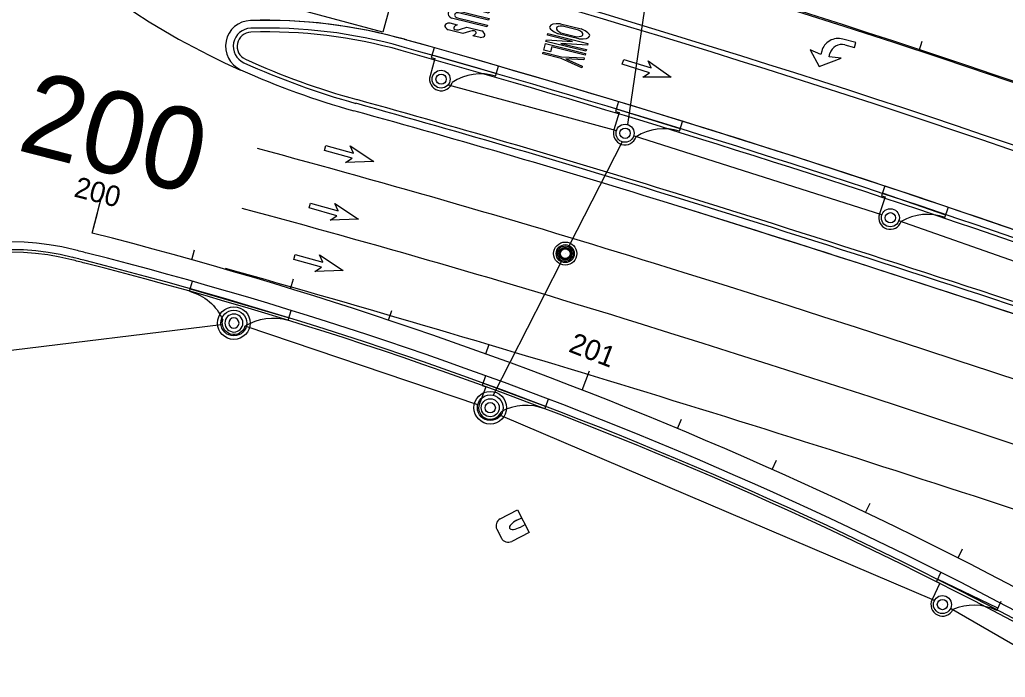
# Model space of a CAD drawing. Extents: x 468143 to 491361, y 1438528 to 1468730.
# Drawn here: x 487025 to 487216.5, y 1467246.7 to 1467374.4 of the extents above; entities that cross this region are included whole.
import ezdxf

# ---------------------------------------------------------------- set-up
doc = ezdxf.new("R2010")
doc.units = 0
doc.layers.add('Default', color=7, linetype='Continuous')
doc.layers.add('Xreference_dp', color=7, linetype='Continuous')

# ---------------------------------------------------------------- blocks, each defined once
blk = doc.blocks.new('POINT_DISPLAY')
at = {"layer": 'Default'}
blk.add_line((0, 0), (0, 0), dxfattribs=at)
blk = doc.blocks.new('InltCurb1_35')
at = {"layer": 'Default'}
for p, q in [((2.25, 2), (2.25, 5.5)), ((-10, 2), (-10, 0)), ((3, 2), (2.25, 2)), ((3, 0), (3, 2)), ((-10, 1.5), (3, 1.5))]:
    blk.add_line(p, q, dxfattribs=at)
for radius in [1.75, 1]:
    blk.add_circle((0, 5.5), radius, dxfattribs=at)
for centre, radius, start, end in [((0, 5.5), 2.25, 0, 180), ((-9.85, 12), 10, 269.1432, 319.4677)]:
    blk.add_arc(centre, radius, start, end, dxfattribs=at)
for p in [(0, 7.75), (-1.6, 6.2), (-1.22, 6.76), (-0.66, 7.12), (0, 7.25), (0, 7.25), (0.7, 7.1), (1.26, 6.72), (1.62, 6.16), (-1.75, 5.5), (-1.75, 5.5), (-1.62, 4.84), (-1.26, 4.28), (-0.7, 3.9), (0, 5.5), (0, 5.5), (0.66, 3.88), (1.22, 4.24), (1.6, 4.8), (1.75, 5.5), (1.75, 5.5), (0, 3.75), (0, 3.75), (0, 0), (0, 0)]:
    blk.add_blockref('POINT_DISPLAY', p, dxfattribs=at)
blk = doc.blocks.new('InltCurb2_35')
at = {"layer": 'Default'}
for p, q in [((-10, 2), (-10, 0)), ((10, 2), (10, 0)), ((-10, 1.5), (10, 1.5))]:
    blk.add_line(p, q, dxfattribs=at)
for radius in [1.75, 1]:
    blk.add_circle((0, 5.5), radius, dxfattribs=at)
for centre, radius, start, end in [((0, 5.5), 2.25, 0, 180), ((-9.85, 12), 10, 269.1432, 319.4677), ((9.85, 12), 10, 220.5323, 270.8568)]:
    blk.add_arc(centre, radius, start, end, dxfattribs=at)
for p in [(0, 7.75), (-1.6, 6.2), (-1.22, 6.76), (-0.66, 7.12), (0, 7.25), (0, 7.25), (0.7, 7.1), (1.26, 6.72), (1.62, 6.16), (-1.75, 5.5), (-1.75, 5.5), (-1.62, 4.84), (-1.26, 4.28), (-0.7, 3.9), (0, 5.5), (0, 5.5), (0.66, 3.88), (1.22, 4.24), (1.6, 4.8), (1.75, 5.5), (1.75, 5.5), (0, 3.75), (0, 3.75), (0, 0), (0, 0)]:
    blk.add_blockref('POINT_DISPLAY', p, dxfattribs=at)
blk = doc.blocks.new('MH2')
at = {"layer": 'Default'}
for p, q in [((-1.25, 0.03), (-1.05, 0.03)), ((-0.9, 0.87), (-0.76, 0.73)), ((-0.87, 0.9), (-0.73, 0.76)), ((-0.03, 1.25), (-0.03, 1.05)), ((0.03, 1.25), (0.03, 1.05)), ((0.87, 0.9), (0.73, 0.76)), ((0.9, 0.87), (0.76, 0.73)), ((1.05, 0.03), (1.25, 0.03)), ((-1.25, -0.03), (-1.05, -0.03)), ((-0.76, -0.73), (-0.9, -0.87)), ((-0.73, -0.76), (-0.87, -0.9)), ((-0.03, -1.05), (-0.03, -1.25)), ((0.03, -1.05), (0.03, -1.25)), ((0.73, -0.76), (0.87, -0.9)), ((0.76, -0.73), (0.9, -0.87)), ((1.05, -0.03), (1.25, -0.03))]:
    blk.add_line(p, q, dxfattribs=at)
for radius in [1.5, 1.25, 1.05, 1, 0.958]:
    blk.add_circle((0, 0), radius, dxfattribs=at)
for p in [(-1, 0), (-0.71, 0.71), (0, 1.5), (0, 1), (0, 0), (0, 0), (0, 0), (0.71, 0.71), (1, 0), (-0.71, -0.71), (0, -1), (0, -1.5), (0.71, -0.71)]:
    blk.add_blockref('POINT_DISPLAY', p, dxfattribs=at)
blk = doc.blocks.new('PBottom35Dia')
at = {"layer": 'Default'}
for radius in [2.25, 1.75, 1.75]:
    blk.add_circle((0, 0), radius, dxfattribs=at)
for p in [(-1.75, 0), (-1.75, 0), (-1.6, 0.7), (-1.22, 1.26), (-0.66, 1.62), (0, 1.75), (0, 1.75), (0, 1.75), (0, 0), (0, 0), (0.7, 1.6), (1.26, 1.22), (1.62, 0.66), (1.75, 0), (1.75, 0), (-1.62, -0.66), (-1.26, -1.22), (-0.7, -1.6), (0, -1.75), (0, -1.75), (0, -1.75), (0.66, -1.62), (1.22, -1.26), (1.6, -0.7)]:
    blk.add_blockref('POINT_DISPLAY', p, dxfattribs=at)
blk = doc.blocks.new('MESS12ECP4S')
at = {"layer": 'Default'}
for p, q in [((0.96, 2.29), (-0.96, 2.29)), ((-2.46, -3.03), (-2.46, 0.79)), ((2.46, 0.79), (2.46, -3.03)), ((2.46, -3.03), (-2.46, -3.03)), ((-0.75, -2), (-0.75, -3.03)), ((0.75, -2), (0.75, -3.03))]:
    blk.add_line(p, q, dxfattribs=at)
for centre, start, end in [((-0.96, 0.79), 90, 180), ((0.96, 0.79), 0, 90)]:
    blk.add_arc(centre, 1.5, start, end, dxfattribs=at)
blk.add_ellipse((0, -2), major_axis=(0, 2), ratio=0.375, start_param=4.712422, end_param=7.853962, dxfattribs=at)
for p in [(0, 2.29), (0, 1.97), (0, 0), (0, 0), (0, -3.03)]:
    blk.add_blockref('POINT_DISPLAY', p, dxfattribs=at)
blk = doc.blocks.new('JBottom50Dia')
at = {"layer": 'Default'}
for radius in [3.17, 2.5, 2.5]:
    blk.add_circle((0, 0), radius, dxfattribs=at)
for p in [(-0.94, 2.32), (0, 2.5), (0, 2.5), (0, 2.5), (1.01, 2.29), (-2.29, 1.01), (-1.74, 1.79), (0, 0), (0, 0), (0, 0), (1.79, 1.74), (2.32, 0.94), (2.5, 0), (2.5, 0), (-2.5, 0), (-2.5, 0), (-2.32, -0.94), (-1.79, -1.74), (1.74, -1.79), (2.29, -1.01), (-1.01, -2.29), (0, -2.5), (0, -2.5), (0, -2.5), (0.94, -2.32)]:
    blk.add_blockref('POINT_DISPLAY', p, dxfattribs=at)
blk = doc.blocks.new('DALeftTurn_1')
at = {"layer": 'Default'}
for points in [[(5.67, 3.17), (2, 0.5), (4.33, 0.83), (4.33, 0.17)], [(6, 0.17), (6, 0.83), (8.25, 0.5), (5.67, 3.17)], [(2, -2.17), (0, -2.17), (0, -3.17), (2.67, -3.17)]]:
    blk.add_lwpolyline(points, dxfattribs=at)
for centre, radius in [((2, 0.17), 2.33), ((2.67, 0.17), 3.33)]:
    blk.add_arc(centre, radius, 270, 0, dxfattribs=at)
blk = doc.blocks.new('DAMerge_2')
at = {"layer": 'Default'}
blk.add_lwpolyline([(0.71, -4.09), (0, -3.39), (3.95, 0.56), (2.42, 0.68), (7.31, 3.21), (4.77, -1.68), (4.66, -0.15), (0.71, -4.09)], dxfattribs=at)
blk = doc.blocks.new('BUS_7')
at = {"layer": 'Default'}
for p, q in [((0, 2.46), (0, 3.17)), ((0, 3.17), (8, 3.17)), ((3.33, 2.83), (1.33, 2.83)), ((1.33, 2.83), (1.33, 2.58)), ((3.33, 2.58), (3.33, 2.83)), ((6.67, 2.83), (4.67, 2.83)), ((4.67, 2.83), (4.67, 2.58)), ((6.67, 2.58), (6.67, 2.83)), ((8, 3.17), (8, 2.46)), ((3.38, 1.83), (0.62, 1.83)), ((0.97, 0.86), (8, 0.86)), ((8, 0.5), (2, 0.5)), ((7.38, 1.83), (4.62, 1.83)), ((8, 0.86), (8, 0.5)), ((0.8, -1.83), (2.26, -1.83)), ((8, -0.83), (0.89, -0.83)), ((2, -0.5), (8, -0.5)), ((3.08, -2.5), (4.23, -1.83)), ((4.23, -1.83), (7.2, -1.83)), ((8, -0.5), (8, -0.83)), ((3.77, -3.17), (0.8, -3.17)), ((4.93, -2.5), (3.77, -3.17)), ((7.2, -3.17), (5.74, -3.17))]:
    blk.add_line(p, q, dxfattribs=at)
for centre, major_axis, ratio, start_param, end_param in [((2, 2.83), (-2.08, 0), 0.64, 0.283794, 0.848062), ((2.33, 2.83), (-1.17, 0), 0.428571, 0.5411, 2.600493), ((2, 2.83), (-2.08, 0), 0.64, 2.293531, 2.857799), ((6, 2.83), (2.08, 0), 0.64, 3.425387, 3.989655), ((5.67, 2.83), (1.17, 0), 0.428571, 3.682692, 5.742086), ((6, 2.83), (2.08, 0), 0.64, 5.435123, 5.999391), ((2, 0), (2, 0), 0.5, 2.110653, 4.126703), ((2, 0), (0.667, 0), 0.75, 1.570796, 4.712389), ((2, -2.5), (-2, 0), 0.416667, 5.35589, 7.210481), ((2.67, -2.17), (-0.877, -0.48), 0.5, 4.914869, 8.056461), ((6, -2.5), (2, 0), 0.416667, 5.35589, 7.210481), ((5.33, -2.83), (-0.869, -0.495), 0.5, 1.760499, 4.902092)]:
    blk.add_ellipse(centre, major_axis=major_axis, ratio=ratio, start_param=start_param, end_param=end_param, dxfattribs=at)
blk = doc.blocks.new('BikeONLY_2')
at = {"layer": 'Default'}
for p, q in [((0.97, 1.833), (3.03, 1.833)), ((2.8, 1.667), (1.2, 1.667)), ((1.2, 1), (2.8, 1)), ((3.03, 0.833), (0.97, 0.833))]:
    blk.add_line(p, q, dxfattribs=at)
for points in [[(0, -0.167), (0, 0), (2.5, 0.458), (0, 0.458), (0, 0.625), (4, 0.625), (4, 0.458), (1.45, 0), (4, 0), (4, -0.167), (0, -0.167)], [(0.667, -1.042), (0, -1.042), (0, -0.375), (4, -0.375), (4, -0.542), (0.667, -0.542), (0.667, -1.042)], [(4, -1.833), (1.833, -1.417), (0, -1.417), (0, -1.25), (1.833, -1.25), (4, -0.833), (4, -1.003), (2.283, -1.333), (4, -1.664), (4, -1.833)]]:
    blk.add_lwpolyline(points, dxfattribs=at)
for major_axis, ratio, start_param, end_param in [((2, 0), 0.291667, 2.111896, 4.171289), ((1.333, 0), 0.3125, 2.214297, 4.068888), ((1.333, 0), 0.3125, 5.35589, 7.210481), ((2, 0), 0.291667, 5.253489, 7.312882)]:
    blk.add_ellipse((2, 1.333), major_axis=major_axis, ratio=ratio, start_param=start_param, end_param=end_param, dxfattribs=at)
blk = doc.blocks.new('DAMerge_6')
at = {"layer": 'Default'}
blk.add_lwpolyline([(0.71, -4.09), (0, -3.39), (3.95, 0.56), (2.42, 0.68), (7.31, 3.21), (4.77, -1.68), (4.66, -0.15), (0.71, -4.09)], dxfattribs=at)
blk = doc.blocks.new('BUS_8')
at = {"layer": 'Default'}
for p, q in [((0, 2.46), (0, 3.17)), ((0, 3.17), (8, 3.17)), ((3.33, 2.83), (1.33, 2.83)), ((1.33, 2.83), (1.33, 2.58)), ((3.33, 2.58), (3.33, 2.83)), ((6.67, 2.83), (4.67, 2.83)), ((4.67, 2.83), (4.67, 2.58)), ((6.67, 2.58), (6.67, 2.83)), ((8, 3.17), (8, 2.46)), ((3.38, 1.83), (0.62, 1.83)), ((0.97, 0.86), (8, 0.86)), ((8, 0.5), (2, 0.5)), ((7.38, 1.83), (4.62, 1.83)), ((8, 0.86), (8, 0.5)), ((0.8, -1.83), (2.26, -1.83)), ((8, -0.83), (0.89, -0.83)), ((2, -0.5), (8, -0.5)), ((3.08, -2.5), (4.23, -1.83)), ((4.23, -1.83), (7.2, -1.83)), ((8, -0.5), (8, -0.83)), ((3.77, -3.17), (0.8, -3.17)), ((4.93, -2.5), (3.77, -3.17)), ((7.2, -3.17), (5.74, -3.17))]:
    blk.add_line(p, q, dxfattribs=at)
for centre, major_axis, ratio, start_param, end_param in [((2, 2.83), (-2.08, 0), 0.64, 0.283794, 0.848062), ((2.33, 2.83), (-1.17, 0), 0.428571, 0.5411, 2.600493), ((2, 2.83), (-2.08, 0), 0.64, 2.293531, 2.857799), ((6, 2.83), (2.08, 0), 0.64, 3.425387, 3.989655), ((5.67, 2.83), (1.17, 0), 0.428571, 3.682692, 5.742086), ((6, 2.83), (2.08, 0), 0.64, 5.435123, 5.999391), ((2, 0), (2, 0), 0.5, 2.110653, 4.126703), ((2, 0), (0.667, 0), 0.75, 1.570796, 4.712389), ((2, -2.5), (-2, 0), 0.416667, 5.35589, 7.210481), ((2.67, -2.17), (-0.877, -0.48), 0.5, 4.914869, 8.056461), ((6, -2.5), (2, 0), 0.416667, 5.35589, 7.210481), ((5.33, -2.83), (-0.869, -0.495), 0.5, 1.760499, 4.902092)]:
    blk.add_ellipse(centre, major_axis=major_axis, ratio=ratio, start_param=start_param, end_param=end_param, dxfattribs=at)
blk = doc.blocks.new('BikeONLY_4')
at = {"layer": 'Default'}
for p, q in [((0.97, 1.833), (3.03, 1.833)), ((2.8, 1.667), (1.2, 1.667)), ((1.2, 1), (2.8, 1)), ((3.03, 0.833), (0.97, 0.833))]:
    blk.add_line(p, q, dxfattribs=at)
for points in [[(0, -0.167), (0, 0), (2.5, 0.458), (0, 0.458), (0, 0.625), (4, 0.625), (4, 0.458), (1.45, 0), (4, 0), (4, -0.167), (0, -0.167)], [(0.667, -1.042), (0, -1.042), (0, -0.375), (4, -0.375), (4, -0.542), (0.667, -0.542), (0.667, -1.042)], [(4, -1.833), (1.833, -1.417), (0, -1.417), (0, -1.25), (1.833, -1.25), (4, -0.833), (4, -1.003), (2.283, -1.333), (4, -1.664), (4, -1.833)]]:
    blk.add_lwpolyline(points, dxfattribs=at)
for major_axis, ratio, start_param, end_param in [((2, 0), 0.291667, 2.111896, 4.171289), ((1.333, 0), 0.3125, 2.214297, 4.068888), ((1.333, 0), 0.3125, 5.35589, 7.210481), ((2, 0), 0.291667, 5.253489, 7.312882)]:
    blk.add_ellipse((2, 1.333), major_axis=major_axis, ratio=ratio, start_param=start_param, end_param=end_param, dxfattribs=at)

msp = doc.modelspace()

# ---------------------------------------------------------------- linework, layer by layer
at = {"layer": 'Xreference_dp'}
for p, q in [((487149.85, 1467400.36), (487143.15, 1467354.07)), ((487199.75, 1467368.38), (487200.38, 1467370.28)), ((487108.26, 1467361.79), (487140.97, 1467352.91)), ((487192.53, 1467336.56), (487144.31, 1467351.88)), ((487142.1, 1467350.73), (487131.81, 1467330.58)), ((487039.14, 1467333.01), (487041.11, 1467340.76)), ((487039.14, 1467333.01), (487040.12, 1467336.88)), ((487262.21, 1467312.03), (487195.84, 1467335.42)), ((487058.46, 1467327.84), (487059, 1467329.77)), ((487130.23, 1467327.45), (487117, 1467301.54)), ((487077.65, 1467322.21), (487078.23, 1467324.12)), ((487096.69, 1467316.11), (487097.33, 1467318)), ((486990.59, 1467306.3), (487064.16, 1467315.29)), ((487114.01, 1467299.65), (487069.04, 1467314.84)), ((487115.59, 1467309.54), (487116.27, 1467311.42)), ((487134.31, 1467302.52), (487135.76, 1467306.25)), ((487202.73, 1467261.63), (487118.46, 1467297.61)), ((487152.86, 1467295.04), (487153.63, 1467296.89)), ((487171.22, 1467287.11), (487172.04, 1467288.94)), ((487189.38, 1467278.73), (487190.24, 1467280.54)), ((487207.33, 1467269.92), (487208.23, 1467271.7)), ((487279.42, 1467217.41), (487205.88, 1467260.11))]:
    msp.add_line(p, q, dxfattribs=at)
msp.add_lwpolyline([(487099.25, 1467385.57), (487095.6, 1467372.06), (487066.64, 1467379.88), (487070.29, 1467393.39)], close=True, dxfattribs=at)
for centre, radius, start, end in [((487129.34, 1467501.5), 150, 166.3971, 245.8239), ((486541.29, 1465374.28), 2185, 65.36901, 75.94924), ((486541.29, 1465374.28), 2184.5, 65.36842, 75.94131), ((486541.29, 1465374.28), 2183, 65.36658, 75.94131), ((486541.29, 1465374.28), 2100, 65.36712, 99.90595), ((486541.29, 1465374.28), 2135, 66.02244, 75.79826), ((487039.15, 1467335.06), 100, 75.7532, 164.5462), ((486541.29, 1465374.28), 2123, 65.38933, 75.79741), ((486541.29, 1465374.28), 2119, 65.36712, 75.79712), ((486541.29, 1465374.28), 2114.75, 65.36712, 75.79712), ((486541.29, 1465374.28), 2115, 65.17986, 75.79712), ((486541.29, 1465374.28), 2100.25, 66.83331, 75.79712), ((486541.29, 1465374.28), 2087.5, 66.11758, 75.79732), ((486541.29, 1465374.28), 2088.5, 66.11758, 75.79731), ((487070.02, 1467369.29), 5, 91.6957, 245.5921), ((487070.02, 1467369.29), 5, 91.6957, 245.5921), ((487072.83, 1467274.34), 100, 74.3712, 91.6957), ((487072.65, 1467272.95), 101.38, 74.2479, 91.5724), ((487070.02, 1467369.29), 3.5, 91.6957, 245.5921), ((487070.02, 1467369.29), 3.5, 91.6957, 245.5921), ((487072.83, 1467274.34), 98.5, 74.3712, 91.6957), ((487070.02, 1467369.29), 2.75, 91.6957, 245.5921), ((487072.83, 1467274.34), 97.75, 74.3712, 91.6957), ((486541.29, 1465374.28), 2073, 67.70446, 74.37116), ((486541.29, 1465374.28), 2073, 65.16596, 74.37116), ((486541.29, 1465374.28), 2071.5, 67.70446, 74.37116), ((487129.94, 1467501.33), 147.75, 245.5921, 254.5311), ((486541.29, 1465374.28), 2070.75, 67.70446, 74.37116), ((487129.94, 1467501.33), 150, 245.5921, 254.5311), ((487129.94, 1467501.33), 150, 245.5921, 254.5311), ((487129.94, 1467501.33), 148.5, 245.5921, 254.5311), ((486541.29, 1465374.28), 2058.5, 72.73052, 74.53105), ((486541.29, 1465374.28), 2059.25, 72.73052, 74.53105), ((486541.29, 1465374.28), 2057, 72.73052, 74.53105), ((486541.29, 1465374.28), 2057, 72.73052, 74.53105), ((486541.29, 1465374.28), 2045, 72.73052, 74.98077), ((486023.86, 1463709.86), 3801.5, 70.00614, 72.73052), ((486023.86, 1463709.86), 3802.25, 70.00614, 72.73052), ((486023.86, 1463709.86), 3800, 70.00614, 72.73052), ((486023.86, 1463709.86), 3800, 66.68453, 72.73052), ((486541.29, 1465374.28), 2033, 72.73052, 74.97653), ((486837.51, 1466539.72), 818.51, 57.54696, 75.73928), ((487023.41, 1467281.28), 50, 75.8122, 163.8517), ((487023.41, 1467281.28), 50, 75.8122, 163.8517), ((487023.41, 1467281.28), 48.5, 75.8122, 163.8517), ((487023.41, 1467281.28), 48, 75.8122, 163.8517), ((486541.29, 1465374.28), 2017, 75.73928, 75.81225), ((486541.29, 1465374.28), 2017, 75.73928, 75.81225), ((486837.51, 1466539.72), 814.51, 57.54696, 75.73928), ((486837.51, 1466539.72), 814.51, 57.54696, 75.73928), ((486541.29, 1465374.28), 2015, 75.73928, 75.81225), ((486541.29, 1465374.28), 2015.5, 75.73928, 75.81225), ((486837.51, 1466539.72), 812.51, 57.54696, 75.73928), ((486837.51, 1466539.72), 813.01, 57.54696, 75.73928), ((486023.86, 1463709.86), 3788, 66.09315, 72.73052), ((486042.49, 1463704.02), 3763.7, 71.63582, 74.236), ((486023.86, 1463709.86), 3776, 66.11865, 72.73052)]:
    msp.add_arc(centre, radius, start, end, dxfattribs=at)

# ---------------------------------------------------------------- block references
for name, p, rotation in [('BUS_7', (487108.25, 1467375.78), -13.849259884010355), ('BUS_8', (487108.25, 1467375.78), -13.849259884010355), ('DALeftTurn_1', (487186.68, 1467366.94), 164.84524802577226), ('InltCurb1_35', (487108.43, 1467368.19), 163.98739698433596), ('DAMerge_2', (487145.39, 1467368.32), -62.46687327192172), ('DAMerge_6', (487145.39, 1467368.32), -62.46687327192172), ('InltCurb1_35', (487144.26, 1467357.65), 162.85943704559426), ('DAMerge_2', (487087.47, 1467351.71), -60.54344010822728), ('DAMerge_6', (487087.47, 1467351.71), -60.54344010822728), ('DAMerge_2', (487084.47, 1467340.52), -60.54344010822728), ('DAMerge_6', (487084.47, 1467340.52), -60.54344010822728), ('InltCurb1_35', (487195.97, 1467341.19), 161.04268344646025), ('DAMerge_2', (487081.49, 1467330.54), -60.54344010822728), ('DAMerge_6', (487081.49, 1467330.54), -60.54344010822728), ('PBottom35Dia', (487131.02, 1467329.02), 86.96945173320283), ('MH2', (487131.02, 1467329.02), 65.36711924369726), ('JBottom50Dia', (487066.64, 1467315.54), 73.59918646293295), ('InltCurb1_35', (487118.37, 1467304.25), 159.570987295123), ('JBottom50Dia', (487116.45, 1467299.1), 77.22888892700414), ('MESS12ECP4S', (487120.21, 1467275.68), 117.30708181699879), ('InltCurb1_35', (487206.69, 1467265.83), 154.36154818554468)]:
    msp.add_blockref(name, p, dxfattribs=dict(at, rotation=rotation))
at = {"layer": 'Xreference_dp', "xscale": 1.9999999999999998, "yscale": 2, "rotation": -13.849259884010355}
for name in ['BikeONLY_2', 'BikeONLY_4']:
    msp.add_blockref(name, (487127.36, 1467370.55), dxfattribs=at)
at = {"layer": 'Xreference_dp', "yscale": -0.9999999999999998, "rotation": -16.445308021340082}
msp.add_blockref('InltCurb2_35', (487068.2, 1467320.82), dxfattribs=at)

# ---------------------------------------------------------------- texts
at = {"layer": 'Xreference_dp'}
for s, height, rotation, p in [('200', 16, 345.7393, (487024.24, 1467349.2)), ('200', 4, 345.7393, (487035.39, 1467340.15)), ('201', 4, 338.7393, (487131.47, 1467310.06))]:
    msp.add_text(s, height=height, rotation=rotation, dxfattribs=at).set_placement(p)

doc.saveas('drawing.dxf')
